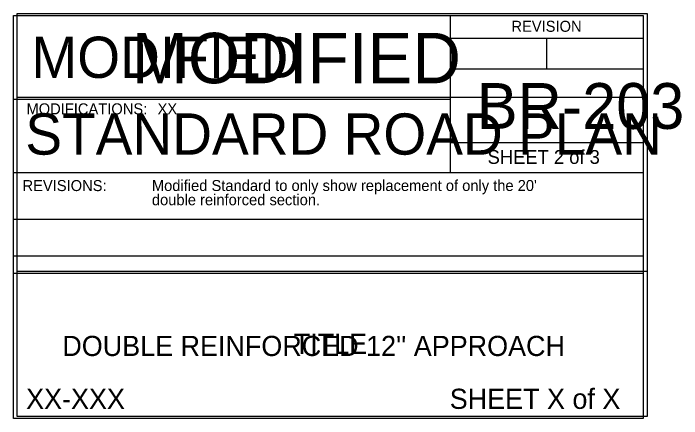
# Model space of a CAD drawing. Extents: x -2135039 to -2124495, y -2139046 to -2132546.
# Drawn here: x -2128887 to -2128157, y -2139046 to -2138604 of the extents above; entities that cross this region are included whole.
import ezdxf

# ---------------------------------------------------------------- set-up
doc = ezdxf.new("R2010")
doc.units = 0
for name, color, linetype in [('Dimension', 7, 'Continuous'), ('dsnAlignmentCurveData', 7, 'Continuous'), ('dsnAlignmentTic', 7, 'Continuous'), ('DsnShtInsideBorder', 7, 'Continuous')]:
    doc.layers.add(name, color=color, linetype=linetype)

msp = doc.modelspace()

# ---------------------------------------------------------------- linework, layer by layer
at = {"layer": 'Dimension'}
for p, q in [((-2128410.36, -2138605.93), (-2128410.36, -2138697.28)), ((-2128410.36, -2138630.88), (-2128199.45, -2138630.88)), ((-2128304.9, -2138630.88), (-2128304.9, -2138664.08)), ((-2128410.36, -2138664.08), (-2128199.45, -2138664.08)), ((-2128887.46, -2138697.28), (-2128410.36, -2138697.28)), ((-2128410.36, -2138697.28), (-2128410.36, -2138777.28)), ((-2128199.45, -2138745.08), (-2128410.36, -2138745.08)), ((-2128887.46, -2138777.28), (-2128199.45, -2138777.28)), ((-2128887.46, -2138828.28), (-2128199.45, -2138828.28)), ((-2128887.46, -2138868.28), (-2128199.45, -2138868.28)), ((-2128887.46, -2138887.28), (-2128199.45, -2138887.28))]:
    msp.add_line(p, q, dxfattribs=at)
msp.add_lwpolyline([(-2128887.46, -2138605.93), (-2128199.45, -2138605.93), (-2128199.45, -2139045.94), (-2128887.46, -2139045.94)], close=True, dxfattribs=at)
msp.add_lwpolyline([(-2128887.46, -2138605.93), (-2128199.45, -2138605.93), (-2128199.45, -2139045.94), (-2128887.46, -2139045.94)], close=True, dxfattribs=at)
at = {"layer": 'DsnShtInsideBorder'}
for p, q in [((-2128883.14, -2138695.03), (-2128195.13, -2138695.03)), ((-2128883.14, -2138885.03), (-2128195.13, -2138885.03))]:
    msp.add_line(p, q, dxfattribs=at)
msp.add_lwpolyline([(-2128883.14, -2138603.69), (-2128195.13, -2138603.69), (-2128195.13, -2139043.7), (-2128883.14, -2139043.7)], close=True, dxfattribs=at)

# ---------------------------------------------------------------- texts
at = {"layer": 'Dimension'}
for s, height, p in [('REVISION', 12, (-2128343.38, -2138623.79)), ('BR-203', 50, (-2128381.18, -2138729.75)), ('STANDARD ROAD PLAN', 45.001, (-2128874.42, -2138757.86)), ('SHEET 2 of 3', 15, (-2128369.41, -2138767.92)), ("Modified Standard to only show replacement of only the 20' ", 12, (-2128736.14, -2138797.54)), ('double reinforced section.', 12, (-2128736.14, -2138813.07)), ("DOUBLE REINFORCED 12'' APPROACH", 22, (-2128833.97, -2138977.61))]:
    msp.add_text(s, height=height, dxfattribs=at).set_placement(p)
at = {"layer": 'dsnAlignmentCurveData'}
msp.add_text('REVISIONS:', height=12, dxfattribs=at).set_placement((-2128877.46, -2138797.61))
at = {"layer": 'dsnAlignmentTic'}
msp.add_text('MODIFIED', height=45.001, dxfattribs=at).set_placement((-2128867.83, -2138674.11))
at = {"layer": 'DsnShtInsideBorder'}
for s, height, p in [('MODIFIED', 55, (-2128758.05, -2138679.94)), ('MODIFICATIONS:', 12, (-2128873.14, -2138713.87)), ('XX', 12, (-2128729.91, -2138713.87)), ('TITLE', 22, (-2128581.06, -2138975.37)), ('XX-XXX', 22, (-2128873.53, -2139035.32)), ('SHEET X of X', 22, (-2128410.76, -2139035.32))]:
    msp.add_text(s, height=height, dxfattribs=at).set_placement(p)

doc.saveas('drawing.dxf')
